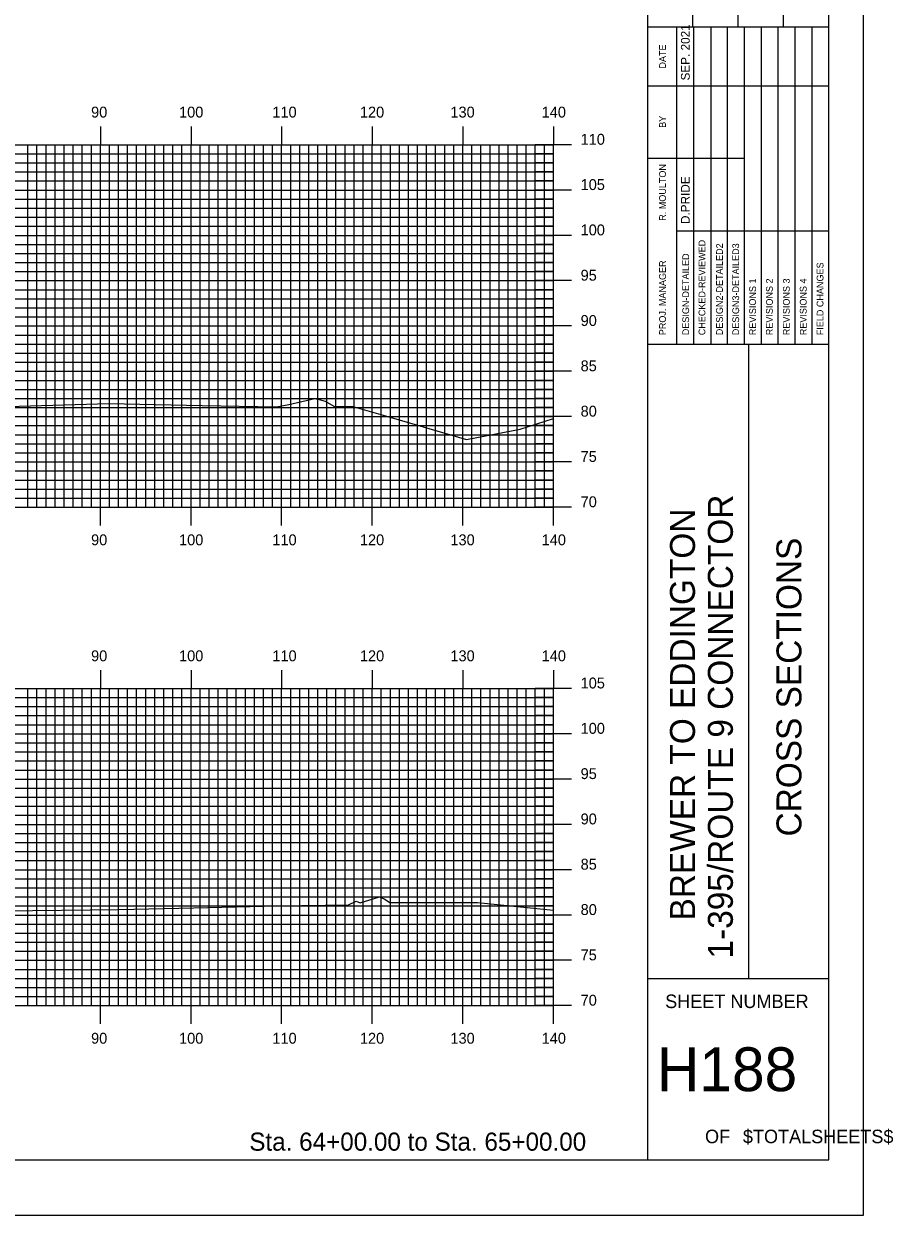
# Model space of a CAD drawing. Extents: x 1758643 to 1758986, y 442591 to 442811.
# Drawn here: x 1758890.2 to 1758986.1, y 442590.5 to 442722 of the extents above; entities that cross this region are included whole.
import ezdxf

# ---------------------------------------------------------------- set-up
doc = ezdxf.new("R2010")
doc.units = 0
for name, color, linetype in [('BORDER', 7, 'Continuous'), ('H_V ANNOTATION', 7, 'Continuous'), ('MAJOR', 7, 'Continuous'), ('MINOR', 7, 'Continuous'), ('PLOT BOUNDARY', 7, 'Continuous'), ('S_Roadway_Centerline', 7, 'Continuous')]:
    doc.layers.add(name, color=color, linetype=linetype)

msp = doc.modelspace()

# ---------------------------------------------------------------- linework, layer by layer
at = {"layer": 'BORDER'}
for p, q in [((1758959.05, 442596.67), (1758959.05, 442806.67)), ((1758964.05, 442721.67), (1758964.05, 442738.97)), ((1758969.05, 442721.67), (1758969.05, 442738.97)), ((1758974.05, 442721.67), (1758974.05, 442738.97)), ((1758959.05, 442721.67), (1758979.05, 442721.67)), ((1758959.05, 442686.67), (1758979.05, 442686.67)), ((1758970.23, 442616.67), (1758970.23, 442686.67)), ((1758959.05, 442616.67), (1758979.05, 442616.67))]:
    msp.add_line(p, q, dxfattribs=at)
msp.add_lwpolyline([(1758659.05, 442596.67), (1758979.05, 442596.67), (1758979.05, 442806.67), (1758659.05, 442806.67)], close=True, dxfattribs=at)
for points in [[(1758962.28, 442715.17), (1758962.28, 442721.67)], [(1758964.14, 442686.68), (1758964.14, 442721.67)], [(1758966.01, 442721.67), (1758966.01, 442686.68)], [(1758967.87, 442686.68), (1758967.87, 442721.67)], [(1758969.73, 442686.68), (1758969.73, 442721.67)], [(1758971.6, 442686.68), (1758971.6, 442721.67)], [(1758973.46, 442686.68), (1758973.46, 442721.67)], [(1758975.32, 442686.68), (1758975.32, 442721.67)], [(1758977.19, 442686.68), (1758977.19, 442721.67)], [(1758962.28, 442686.68), (1758962.28, 442720.26)], [(1758959.05, 442715.17), (1758979.05, 442715.17)], [(1758959.05, 442707.17), (1758962.28, 442707.17)], [(1758962.28, 442707.17), (1758969.73, 442707.17)], [(1758962.28, 442699.17), (1758979.05, 442699.17)]]:
    msp.add_lwpolyline(points, dxfattribs=at)
at = {"layer": 'MAJOR'}
for p, q in [((1758898.65, 442710.67), (1758898.65, 442708.67)), ((1758908.65, 442710.67), (1758908.65, 442708.67)), ((1758918.65, 442710.67), (1758918.65, 442708.67)), ((1758928.65, 442710.67), (1758928.65, 442708.67)), ((1758938.65, 442710.67), (1758938.65, 442708.67)), ((1758948.65, 442710.67), (1758948.65, 442708.67)), ((1758668.65, 442708.67), (1758948.65, 442708.67)), ((1758668.65, 442708.67), (1758948.65, 442708.67)), ((1758898.65, 442668.67), (1758898.65, 442708.67)), ((1758908.65, 442668.67), (1758908.65, 442708.67)), ((1758918.65, 442668.67), (1758918.65, 442708.67)), ((1758928.65, 442668.67), (1758928.65, 442708.67)), ((1758938.65, 442668.67), (1758938.65, 442708.67)), ((1758950.65, 442708.67), (1758946.64, 442708.67)), ((1758948.65, 442668.67), (1758948.65, 442708.67)), ((1758948.65, 442668.67), (1758948.65, 442708.67)), ((1758668.65, 442703.67), (1758948.65, 442703.67)), ((1758950.65, 442703.67), (1758946.64, 442703.67)), ((1758668.65, 442698.67), (1758948.65, 442698.67)), ((1758950.65, 442698.67), (1758946.64, 442698.67)), ((1758668.65, 442693.67), (1758948.65, 442693.67)), ((1758950.65, 442693.67), (1758946.64, 442693.67)), ((1758668.65, 442688.67), (1758948.65, 442688.67)), ((1758950.65, 442688.67), (1758946.64, 442688.67)), ((1758668.65, 442683.67), (1758948.65, 442683.67)), ((1758950.65, 442683.67), (1758946.64, 442683.67)), ((1758668.65, 442678.67), (1758948.65, 442678.67)), ((1758950.65, 442678.67), (1758946.64, 442678.67)), ((1758668.65, 442673.67), (1758948.65, 442673.67)), ((1758950.65, 442673.67), (1758946.64, 442673.67)), ((1758668.65, 442668.67), (1758948.65, 442668.67)), ((1758668.65, 442668.67), (1758948.65, 442668.67)), ((1758898.65, 442666.66), (1758898.65, 442668.67)), ((1758908.65, 442666.66), (1758908.65, 442668.67)), ((1758918.65, 442666.66), (1758918.65, 442668.67)), ((1758928.65, 442666.66), (1758928.65, 442668.67)), ((1758938.65, 442666.66), (1758938.65, 442668.67)), ((1758950.65, 442668.67), (1758946.64, 442668.67)), ((1758948.65, 442666.66), (1758948.65, 442668.67)), ((1758898.65, 442650.67), (1758898.65, 442648.67)), ((1758908.65, 442650.67), (1758908.65, 442648.67)), ((1758918.65, 442650.67), (1758918.65, 442648.67)), ((1758928.65, 442650.67), (1758928.65, 442648.67)), ((1758938.65, 442650.67), (1758938.65, 442648.67)), ((1758948.65, 442650.67), (1758948.65, 442648.67)), ((1758668.65, 442648.67), (1758948.65, 442648.67)), ((1758668.65, 442648.67), (1758948.65, 442648.67)), ((1758898.65, 442613.67), (1758898.65, 442648.67)), ((1758908.65, 442613.67), (1758908.65, 442648.67)), ((1758918.65, 442613.67), (1758918.65, 442648.67)), ((1758928.65, 442613.67), (1758928.65, 442648.67)), ((1758938.65, 442613.67), (1758938.65, 442648.67)), ((1758950.65, 442648.67), (1758946.64, 442648.67)), ((1758948.65, 442613.67), (1758948.65, 442648.67)), ((1758948.65, 442613.67), (1758948.65, 442648.67)), ((1758668.65, 442643.67), (1758948.65, 442643.67)), ((1758950.65, 442643.67), (1758946.64, 442643.67)), ((1758668.65, 442638.67), (1758948.65, 442638.67)), ((1758950.65, 442638.67), (1758946.64, 442638.67)), ((1758668.65, 442633.67), (1758948.65, 442633.67)), ((1758950.65, 442633.67), (1758946.64, 442633.67)), ((1758668.65, 442628.67), (1758948.65, 442628.67)), ((1758950.65, 442628.67), (1758946.64, 442628.67)), ((1758668.65, 442623.67), (1758948.65, 442623.67)), ((1758950.65, 442623.67), (1758946.64, 442623.67)), ((1758668.65, 442618.67), (1758948.65, 442618.67)), ((1758950.65, 442618.67), (1758946.64, 442618.67)), ((1758668.65, 442613.67), (1758948.65, 442613.67)), ((1758668.65, 442613.67), (1758948.65, 442613.67)), ((1758898.65, 442611.66), (1758898.65, 442613.67)), ((1758908.65, 442611.66), (1758908.65, 442613.67)), ((1758918.65, 442611.66), (1758918.65, 442613.67)), ((1758928.65, 442611.66), (1758928.65, 442613.67)), ((1758938.65, 442611.66), (1758938.65, 442613.67)), ((1758950.65, 442613.67), (1758946.64, 442613.67)), ((1758948.65, 442611.66), (1758948.65, 442613.67))]:
    msp.add_line(p, q, dxfattribs=at)
at = {"layer": 'MINOR'}
for p, q in [((1758890.65, 442668.67), (1758890.65, 442708.67)), ((1758891.65, 442668.67), (1758891.65, 442708.67)), ((1758892.65, 442668.67), (1758892.65, 442708.67)), ((1758893.65, 442668.67), (1758893.65, 442708.67)), ((1758894.65, 442668.67), (1758894.65, 442708.67)), ((1758895.65, 442668.67), (1758895.65, 442708.67)), ((1758896.65, 442668.67), (1758896.65, 442708.67)), ((1758897.65, 442668.67), (1758897.65, 442708.67)), ((1758899.65, 442668.67), (1758899.65, 442708.67)), ((1758900.65, 442668.67), (1758900.65, 442708.67)), ((1758901.65, 442668.67), (1758901.65, 442708.67)), ((1758902.65, 442668.67), (1758902.65, 442708.67)), ((1758903.65, 442668.67), (1758903.65, 442708.67)), ((1758904.65, 442668.67), (1758904.65, 442708.67)), ((1758905.65, 442668.67), (1758905.65, 442708.67)), ((1758906.65, 442668.67), (1758906.65, 442708.67)), ((1758907.65, 442668.67), (1758907.65, 442708.67)), ((1758909.65, 442668.67), (1758909.65, 442708.67)), ((1758910.65, 442668.67), (1758910.65, 442708.67)), ((1758911.65, 442668.67), (1758911.65, 442708.67)), ((1758912.65, 442668.67), (1758912.65, 442708.67)), ((1758913.65, 442668.67), (1758913.65, 442708.67)), ((1758914.65, 442668.67), (1758914.65, 442708.67)), ((1758915.65, 442668.67), (1758915.65, 442708.67)), ((1758916.65, 442668.67), (1758916.65, 442708.67)), ((1758917.65, 442668.67), (1758917.65, 442708.67)), ((1758919.65, 442668.67), (1758919.65, 442708.67)), ((1758920.65, 442668.67), (1758920.65, 442708.67)), ((1758921.65, 442668.67), (1758921.65, 442708.67)), ((1758922.65, 442668.67), (1758922.65, 442708.67)), ((1758923.65, 442668.67), (1758923.65, 442708.67)), ((1758924.65, 442668.67), (1758924.65, 442708.67)), ((1758925.65, 442668.67), (1758925.65, 442708.67)), ((1758926.65, 442668.67), (1758926.65, 442708.67)), ((1758927.65, 442668.67), (1758927.65, 442708.67)), ((1758929.65, 442668.67), (1758929.65, 442708.67)), ((1758930.65, 442668.67), (1758930.65, 442708.67)), ((1758931.65, 442668.67), (1758931.65, 442708.67)), ((1758932.65, 442668.67), (1758932.65, 442708.67)), ((1758933.65, 442668.67), (1758933.65, 442708.67)), ((1758934.65, 442668.67), (1758934.65, 442708.67)), ((1758935.65, 442668.67), (1758935.65, 442708.67)), ((1758936.65, 442668.67), (1758936.65, 442708.67)), ((1758937.65, 442668.67), (1758937.65, 442708.67)), ((1758939.65, 442668.67), (1758939.65, 442708.67)), ((1758940.65, 442668.67), (1758940.65, 442708.67)), ((1758941.65, 442668.67), (1758941.65, 442708.67)), ((1758942.65, 442668.67), (1758942.65, 442708.67)), ((1758943.65, 442668.67), (1758943.65, 442708.67)), ((1758944.65, 442668.67), (1758944.65, 442708.67)), ((1758945.65, 442668.67), (1758945.65, 442708.67)), ((1758946.65, 442668.67), (1758946.65, 442708.67)), ((1758947.65, 442668.67), (1758947.65, 442708.67)), ((1758668.65, 442707.67), (1758948.65, 442707.67)), ((1758948.65, 442707.67), (1758946.64, 442707.67)), ((1758668.65, 442706.67), (1758948.65, 442706.67)), ((1758668.65, 442705.67), (1758948.65, 442705.67)), ((1758948.65, 442706.67), (1758946.64, 442706.67)), ((1758948.65, 442705.67), (1758946.64, 442705.67)), ((1758668.65, 442704.67), (1758948.65, 442704.67)), ((1758948.65, 442704.67), (1758946.64, 442704.67)), ((1758668.65, 442702.67), (1758948.65, 442702.67)), ((1758668.65, 442701.67), (1758948.65, 442701.67)), ((1758948.65, 442702.67), (1758946.64, 442702.67)), ((1758948.65, 442701.67), (1758946.64, 442701.67)), ((1758668.65, 442700.67), (1758948.65, 442700.67)), ((1758948.65, 442700.67), (1758946.64, 442700.67)), ((1758668.65, 442699.67), (1758948.65, 442699.67)), ((1758948.65, 442699.67), (1758946.64, 442699.67)), ((1758668.65, 442697.67), (1758948.65, 442697.67)), ((1758948.65, 442697.67), (1758946.64, 442697.67)), ((1758668.65, 442696.67), (1758948.65, 442696.67)), ((1758948.65, 442696.67), (1758946.64, 442696.67)), ((1758668.65, 442695.67), (1758948.65, 442695.67)), ((1758948.65, 442695.67), (1758946.64, 442695.67)), ((1758668.65, 442694.67), (1758948.65, 442694.67)), ((1758948.65, 442694.67), (1758946.64, 442694.67)), ((1758668.65, 442692.67), (1758948.65, 442692.67)), ((1758948.65, 442692.67), (1758946.64, 442692.67)), ((1758668.65, 442691.67), (1758948.65, 442691.67)), ((1758948.65, 442691.67), (1758946.64, 442691.67)), ((1758668.65, 442690.67), (1758948.65, 442690.67)), ((1758948.65, 442690.67), (1758946.64, 442690.67)), ((1758668.65, 442689.67), (1758948.65, 442689.67)), ((1758948.65, 442689.67), (1758946.64, 442689.67)), ((1758668.65, 442687.67), (1758948.65, 442687.67)), ((1758948.65, 442687.67), (1758946.64, 442687.67)), ((1758668.65, 442686.67), (1758948.65, 442686.67)), ((1758948.65, 442686.67), (1758946.64, 442686.67)), ((1758668.65, 442685.67), (1758948.65, 442685.67)), ((1758668.65, 442684.67), (1758948.65, 442684.67)), ((1758948.65, 442685.67), (1758946.64, 442685.67)), ((1758948.65, 442684.67), (1758946.64, 442684.67)), ((1758668.65, 442682.67), (1758948.65, 442682.67)), ((1758948.65, 442682.67), (1758946.64, 442682.67)), ((1758668.65, 442681.67), (1758948.65, 442681.67)), ((1758668.65, 442680.67), (1758948.65, 442680.67)), ((1758948.65, 442681.67), (1758946.64, 442681.67)), ((1758948.65, 442680.67), (1758946.64, 442680.67)), ((1758668.65, 442679.67), (1758948.65, 442679.67)), ((1758948.65, 442679.67), (1758946.64, 442679.67)), ((1758668.65, 442677.67), (1758948.65, 442677.67)), ((1758668.65, 442676.67), (1758948.65, 442676.67)), ((1758948.65, 442677.67), (1758946.64, 442677.67)), ((1758948.65, 442676.67), (1758946.64, 442676.67)), ((1758668.65, 442675.67), (1758948.65, 442675.67)), ((1758948.65, 442675.67), (1758946.64, 442675.67)), ((1758668.65, 442674.67), (1758948.65, 442674.67)), ((1758948.65, 442674.67), (1758946.64, 442674.67)), ((1758668.65, 442672.67), (1758948.65, 442672.67)), ((1758948.65, 442672.67), (1758946.64, 442672.67)), ((1758668.65, 442671.67), (1758948.65, 442671.67)), ((1758948.65, 442671.67), (1758946.64, 442671.67)), ((1758668.65, 442670.67), (1758948.65, 442670.67)), ((1758948.65, 442670.67), (1758946.64, 442670.67)), ((1758668.65, 442669.67), (1758948.65, 442669.67)), ((1758948.65, 442669.67), (1758946.64, 442669.67)), ((1758668.65, 442647.67), (1758948.65, 442647.67)), ((1758890.65, 442613.67), (1758890.65, 442648.67)), ((1758891.65, 442613.67), (1758891.65, 442648.67)), ((1758892.65, 442613.67), (1758892.65, 442648.67)), ((1758893.65, 442613.67), (1758893.65, 442648.67)), ((1758894.65, 442613.67), (1758894.65, 442648.67)), ((1758895.65, 442613.67), (1758895.65, 442648.67)), ((1758896.65, 442613.67), (1758896.65, 442648.67)), ((1758897.65, 442613.67), (1758897.65, 442648.67)), ((1758899.65, 442613.67), (1758899.65, 442648.67)), ((1758900.65, 442613.67), (1758900.65, 442648.67)), ((1758901.65, 442613.67), (1758901.65, 442648.67)), ((1758902.65, 442613.67), (1758902.65, 442648.67)), ((1758903.65, 442613.67), (1758903.65, 442648.67)), ((1758904.65, 442613.67), (1758904.65, 442648.67)), ((1758905.65, 442613.67), (1758905.65, 442648.67)), ((1758906.65, 442613.67), (1758906.65, 442648.67)), ((1758907.65, 442613.67), (1758907.65, 442648.67)), ((1758909.65, 442613.67), (1758909.65, 442648.67)), ((1758910.65, 442613.67), (1758910.65, 442648.67)), ((1758911.65, 442613.67), (1758911.65, 442648.67)), ((1758912.65, 442613.67), (1758912.65, 442648.67)), ((1758913.65, 442613.67), (1758913.65, 442648.67)), ((1758914.65, 442613.67), (1758914.65, 442648.67)), ((1758915.65, 442613.67), (1758915.65, 442648.67)), ((1758916.65, 442613.67), (1758916.65, 442648.67)), ((1758917.65, 442613.67), (1758917.65, 442648.67)), ((1758919.65, 442613.67), (1758919.65, 442648.67)), ((1758920.65, 442613.67), (1758920.65, 442648.67)), ((1758921.65, 442613.67), (1758921.65, 442648.67)), ((1758922.65, 442613.67), (1758922.65, 442648.67)), ((1758923.65, 442613.67), (1758923.65, 442648.67)), ((1758924.65, 442613.67), (1758924.65, 442648.67)), ((1758925.65, 442613.67), (1758925.65, 442648.67)), ((1758926.65, 442613.67), (1758926.65, 442648.67)), ((1758927.65, 442613.67), (1758927.65, 442648.67)), ((1758929.65, 442613.67), (1758929.65, 442648.67)), ((1758930.65, 442613.67), (1758930.65, 442648.67)), ((1758931.65, 442613.67), (1758931.65, 442648.67)), ((1758932.65, 442613.67), (1758932.65, 442648.67)), ((1758933.65, 442613.67), (1758933.65, 442648.67)), ((1758934.65, 442613.67), (1758934.65, 442648.67)), ((1758935.65, 442613.67), (1758935.65, 442648.67)), ((1758936.65, 442613.67), (1758936.65, 442648.67)), ((1758937.65, 442613.67), (1758937.65, 442648.67)), ((1758939.65, 442613.67), (1758939.65, 442648.67)), ((1758940.65, 442613.67), (1758940.65, 442648.67)), ((1758941.65, 442613.67), (1758941.65, 442648.67)), ((1758942.65, 442613.67), (1758942.65, 442648.67)), ((1758943.65, 442613.67), (1758943.65, 442648.67)), ((1758944.65, 442613.67), (1758944.65, 442648.67)), ((1758945.65, 442613.67), (1758945.65, 442648.67)), ((1758948.65, 442647.67), (1758946.64, 442647.67)), ((1758946.65, 442613.67), (1758946.65, 442648.67)), ((1758947.65, 442613.67), (1758947.65, 442648.67)), ((1758668.65, 442646.67), (1758948.65, 442646.67)), ((1758948.65, 442646.67), (1758946.64, 442646.67)), ((1758668.65, 442645.67), (1758948.65, 442645.67)), ((1758948.65, 442645.67), (1758946.64, 442645.67)), ((1758668.65, 442644.67), (1758948.65, 442644.67)), ((1758948.65, 442644.67), (1758946.64, 442644.67)), ((1758668.65, 442642.67), (1758948.65, 442642.67)), ((1758948.65, 442642.67), (1758946.64, 442642.67)), ((1758668.65, 442641.67), (1758948.65, 442641.67)), ((1758948.65, 442641.67), (1758946.64, 442641.67)), ((1758668.65, 442640.67), (1758948.65, 442640.67)), ((1758948.65, 442640.67), (1758946.64, 442640.67)), ((1758668.65, 442639.67), (1758948.65, 442639.67)), ((1758948.65, 442639.67), (1758946.64, 442639.67)), ((1758668.65, 442637.67), (1758948.65, 442637.67)), ((1758948.65, 442637.67), (1758946.64, 442637.67)), ((1758668.65, 442636.67), (1758948.65, 442636.67)), ((1758948.65, 442636.67), (1758946.64, 442636.67)), ((1758668.65, 442635.67), (1758948.65, 442635.67)), ((1758668.65, 442634.67), (1758948.65, 442634.67)), ((1758948.65, 442635.67), (1758946.64, 442635.67)), ((1758948.65, 442634.67), (1758946.64, 442634.67)), ((1758668.65, 442632.67), (1758948.65, 442632.67)), ((1758948.65, 442632.67), (1758946.64, 442632.67)), ((1758668.65, 442631.67), (1758948.65, 442631.67)), ((1758668.65, 442630.67), (1758948.65, 442630.67)), ((1758948.65, 442631.67), (1758946.64, 442631.67)), ((1758948.65, 442630.67), (1758946.64, 442630.67)), ((1758668.65, 442629.67), (1758948.65, 442629.67)), ((1758948.65, 442629.67), (1758946.64, 442629.67)), ((1758668.65, 442627.67), (1758948.65, 442627.67)), ((1758668.65, 442626.67), (1758948.65, 442626.67)), ((1758948.65, 442627.67), (1758946.64, 442627.67)), ((1758948.65, 442626.67), (1758946.64, 442626.67)), ((1758668.65, 442625.67), (1758948.65, 442625.67)), ((1758948.65, 442625.67), (1758946.64, 442625.67)), ((1758668.65, 442624.67), (1758948.65, 442624.67)), ((1758948.65, 442624.67), (1758946.64, 442624.67)), ((1758668.65, 442622.67), (1758948.65, 442622.67)), ((1758948.65, 442622.67), (1758946.64, 442622.67)), ((1758668.65, 442621.67), (1758948.65, 442621.67)), ((1758948.65, 442621.67), (1758946.64, 442621.67)), ((1758668.65, 442620.67), (1758948.65, 442620.67)), ((1758948.65, 442620.67), (1758946.64, 442620.67)), ((1758668.65, 442619.67), (1758948.65, 442619.67)), ((1758948.65, 442619.67), (1758946.64, 442619.67)), ((1758668.65, 442617.67), (1758948.65, 442617.67)), ((1758948.65, 442617.67), (1758946.64, 442617.67)), ((1758668.65, 442616.67), (1758948.65, 442616.67)), ((1758948.65, 442616.67), (1758946.64, 442616.67)), ((1758668.65, 442615.67), (1758948.65, 442615.67)), ((1758948.65, 442615.67), (1758946.64, 442615.67)), ((1758668.65, 442614.67), (1758948.65, 442614.67)), ((1758948.65, 442614.67), (1758946.64, 442614.67))]:
    msp.add_line(p, q, dxfattribs=at)
at = {"layer": 'PLOT BOUNDARY'}
msp.add_lwpolyline([(1758642.86, 442590.55), (1758982.86, 442590.55), (1758982.86, 442810.55), (1758642.86, 442810.55)], close=True, dxfattribs=at)
at = {"layer": 'S_Roadway_Centerline'}
for points in [[(1758885.94, 442679.72), (1758899.57, 442680.1), (1758909.87, 442679.88), (1758918.09, 442679.73), (1758919.46, 442680), (1758922.32, 442680.65), (1758922.79, 442680.54), (1758923.44, 442680.38), (1758924.41, 442679.83), (1758926.51, 442679.8), (1758930.13, 442678.76), (1758939.05, 442676.13), (1758944.97, 442677.3), (1758948.65, 442678.46)], [(1758887.99, 442624.14), (1758900.68, 442624.27), (1758908.97, 442624.48), (1758918.26, 442624.69), (1758926.03, 442624.79), (1758926.86, 442625.18), (1758927.3, 442625.03), (1758929.44, 442625.68), (1758929.96, 442625.46), (1758930.61, 442625.06), (1758940.25, 442625.04), (1758948.65, 442624.21)]]:
    msp.add_lwpolyline(points, dxfattribs=at)

# ---------------------------------------------------------------- texts
at = {"layer": 'BORDER'}
for s, height, p in [('SEP. 2021', 0.969, (1758963.69, 442715.76)), ('DATE', 0.743, (1758961.06, 442717.08)), ('BY', 0.743, (1758961.06, 442710.54)), ('R. MOULTON', 0.745, (1758961.06, 442700.28)), ('D.PRIDE', 0.969, (1758963.69, 442699.92)), ('CHECKED-REVIEWED', 0.7455, (1758965.41, 442687.65)), ('DESIGN2-DETAILED2', 0.7455, (1758967.35, 442687.65)), ('DESIGN3-DETAILED3', 0.7455, (1758969.14, 442687.65)), ('DESIGN-DETAILED', 0.7455, (1758963.62, 442687.65)), ('PROJ. MANAGER', 0.7455, (1758961.06, 442687.65)), ('FIELD CHANGES', 0.7455, (1758978.45, 442687.65)), ('REVISIONS 1', 0.7455, (1758971, 442687.65)), ('REVISIONS 2', 0.7455, (1758972.86, 442687.65)), ('REVISIONS 3', 0.7455, (1758974.73, 442687.65)), ('REVISIONS 4', 0.7455, (1758976.59, 442687.65)), ('1-395/ROUTE 9 CONNECTOR', 2.7557, (1758968.45, 442618.87)), ('BREWER TO EDDINGTON', 2.7557, (1758964.27, 442623.07)), ('CROSS SECTIONS', 2.7557, (1758976.02, 442632.34))]:
    msp.add_text(s, height=height, rotation=90, dxfattribs=at).set_placement(p)
for s, height, p in [('SHEET NUMBER', 1.4905, (1758960.98, 442613.4)), ('H188', 4.839, (1758960.08, 442604.23)), ('OF', 1.491, (1758965.38, 442598.49)), ('$TOTALSHEETS$', 1.4905, (1758969.56, 442598.49))]:
    msp.add_text(s, height=height, dxfattribs=at).set_placement(p)
at = {"layer": 'H_V ANNOTATION'}
for s, height, p in [('90', 1.2, (1758897.62, 442711.67)), ('100', 1.2, (1758907.33, 442711.67)), ('110', 1.2, (1758917.63, 442711.67)), ('120', 1.2, (1758927.29, 442711.67)), ('130', 1.2, (1758937.28, 442711.67)), ('140', 1.2, (1758947.35, 442711.67)), ('110', 1.2, (1758951.65, 442708.67)), ('105', 1.2, (1758951.65, 442703.67)), ('100', 1.2, (1758951.65, 442698.67)), ('95', 1.2, (1758951.65, 442693.67)), ('90', 1.2, (1758951.65, 442688.67)), ('85', 1.2, (1758951.65, 442683.67)), ('80', 1.2, (1758951.65, 442678.67)), ('75', 1.2, (1758951.65, 442673.67)), ('70', 1.2, (1758951.65, 442668.67)), ('90', 1.2, (1758897.62, 442664.47)), ('100', 1.2, (1758907.33, 442664.47)), ('110', 1.2, (1758917.63, 442664.47)), ('120', 1.2, (1758927.29, 442664.47)), ('130', 1.2, (1758937.28, 442664.47)), ('140', 1.2, (1758947.35, 442664.47)), ('90', 1.2, (1758897.62, 442651.67)), ('100', 1.2, (1758907.33, 442651.67)), ('110', 1.2, (1758917.63, 442651.67)), ('120', 1.2, (1758927.29, 442651.67)), ('130', 1.2, (1758937.28, 442651.67)), ('140', 1.2, (1758947.35, 442651.67)), ('105', 1.2, (1758951.65, 442648.67)), ('100', 1.2, (1758951.65, 442643.67)), ('95', 1.2, (1758951.65, 442638.67)), ('90', 1.2, (1758951.65, 442633.67)), ('85', 1.2, (1758951.65, 442628.67)), ('80', 1.2, (1758951.65, 442623.67)), ('75', 1.2, (1758951.65, 442618.67)), ('70', 1.2, (1758951.65, 442613.67)), ('90', 1.2, (1758897.62, 442609.47)), ('100', 1.2, (1758907.33, 442609.47)), ('110', 1.2, (1758917.63, 442609.47)), ('120', 1.2, (1758927.29, 442609.47)), ('130', 1.2, (1758937.28, 442609.47)), ('140', 1.2, (1758947.35, 442609.47)), ('Sta. 64+00.00 to Sta. 65+00.00', 2.0004, (1758915.08, 442597.66))]:
    msp.add_text(s, height=height, dxfattribs=at).set_placement(p)

doc.saveas('drawing.dxf')
